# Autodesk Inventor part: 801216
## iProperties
Author: kreutmayr
Shininess: 20.0
Angle Display Precision: 2
Document Length Units: 11269
Document Angle Units: 11283
Document Time Units: 11279
Document Mass Units: 11290
Document Length Units Precision: 3
Document Angle Units Precision: 2
Compacted: False
PropertySet Name: _Private Model Information
Created: 2002-05
Part Number: 801216
Material: 1.4301 X5CrNi10-10 A2
Description: NF Rohr LS 03
Document SubType Name: Blech
Designer: kreutmayr
Control State: 0
Master: False
Checked Out: False
PropertySet Name: Design Tracking Control
Density: 0.0
Volumn: 0.0
Area: 0.0
PropertySet Name: Model Information
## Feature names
1. Extrusion6
2. Trennen1
3. Extrusion9
4. Trennen3
5. ExtrusionAbwicklung1
